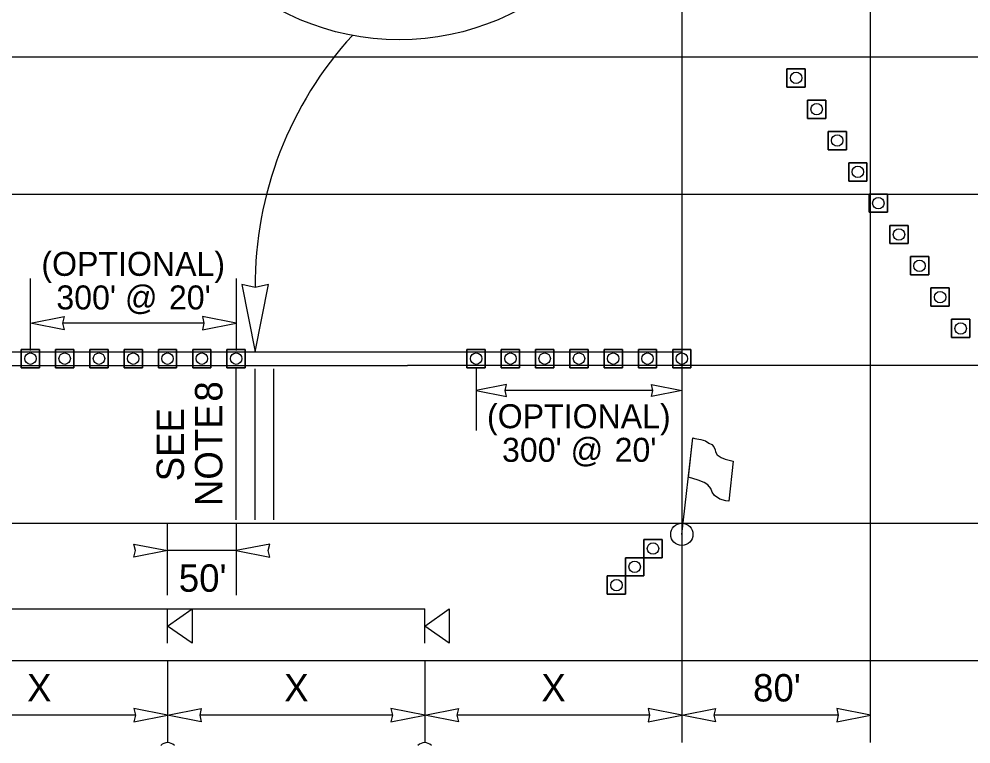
# Model space of a CAD drawing. Extents: x 99999.1 to 100095.7, y 99995 to 100010.7.
# Drawn here: x 100042.344 to 100045.12, y 100005.488 to 100007.603 of the extents above; entities that cross this region are included whole.
import ezdxf

# ---------------------------------------------------------------- set-up
doc = ezdxf.new("R2010")
doc.units = 0
for name, color, linetype in [('RD_ED_ShoulderPavedEdge', 7, 'Continuous'), ('RD_MK_LineDblYellowCenter', 7, 'Continuous'), ('RD_MK_LineEdgeWhite', 7, 'Continuous'), ('RD_MK_LineNoPass', 7, 'Continuous'), ('RD_MK_LineSkipCenter', 7, 'Continuous'), ('TR_SN_ConstructionSigns', 7, 'Continuous'), ('TR_WZ_FlaggingStation', 7, 'Continuous'), ('TR_WZ_PortableSignMountBlk-Org', 7, 'Continuous'), ('TR_WZ_TrafficCone', 7, 'Continuous'), ('TR_WZ_WorkZoneDetails', 7, 'Continuous'), ('TR_WZ_WorkZoneTextCurrent', 7, 'Continuous')]:
    doc.layers.add(name, color=color, linetype=linetype)

msp = doc.modelspace()

# ---------------------------------------------------------------- linework, layer by layer
at = {"layer": 'RD_ED_ShoulderPavedEdge'}
for p, q in [((100040.1076, 100007.4923), (100055.6424, 100007.4923)), ((100040.1076, 100005.7323), (100055.6424, 100005.7323))]:
    msp.add_line(p, q, dxfattribs=at)
at = {"layer": 'RD_MK_LineDblYellowCenter'}
for p, q in [((100040.1282, 100006.6323), (100043.4767, 100006.6323)), ((100040.0869, 100006.5923), (100043.4767, 100006.5923))]:
    msp.add_line(p, q, dxfattribs=at)
at = {"layer": 'RD_MK_LineEdgeWhite'}
for p, q in [((100040.1076, 100007.0923), (100055.6424, 100007.0923)), ((100040.1076, 100006.1323), (100055.6424, 100006.1323))]:
    msp.add_line(p, q, dxfattribs=at)
at = {"layer": 'RD_MK_LineNoPass'}
msp.add_line((100043.4767, 100006.6323), (100044.2767, 100006.6323), dxfattribs=at)
at = {"layer": 'RD_MK_LineSkipCenter'}
msp.add_lwpolyline([(100051.15, 100006.5923), (100043.4767, 100006.5923)], dxfattribs=at)
at = {"layer": 'TR_SN_ConstructionSigns'}
for centre in [(100042.7767, 100005.4642), (100043.5267, 100005.4642)]:
    msp.add_arc(centre, 0.0281, 45, 135, dxfattribs=at)
at = {"layer": 'TR_WZ_FlaggingStation'}
for p, q in [((100044.2767, 100006.0998), (100044.3087, 100006.3808)), ((100044.2957, 100006.2667), (100044.3087, 100006.3811)), ((100044.4267, 100006.3133), (100044.4134, 100006.1961)), ((100044.2957, 100006.2667), (100044.2957, 100006.2667))]:
    msp.add_line(p, q, dxfattribs=at)
for points in [[(100044.3087, 100006.3811), (100044.3145, 100006.3798), (100044.3323, 100006.3764), (100044.3461, 100006.3722), (100044.3558, 100006.3661), (100044.3643, 100006.3614), (100044.37, 100006.3546), (100044.3743, 100006.3467), (100044.3748, 100006.3405), (100044.3802, 100006.3313), (100044.391, 100006.3239), (100044.4034, 100006.3187), (100044.4267, 100006.3133)], [(100044.4134, 100006.1961), (100044.4052, 100006.1975), (100044.3876, 100006.2021), (100044.3719, 100006.2126), (100044.3654, 100006.2232), (100044.3615, 100006.2335), (100044.3524, 100006.2444), (100044.3414, 100006.2506), (100044.3241, 100006.2577), (100044.2957, 100006.2667)]]:
    msp.add_lwpolyline(points, dxfattribs=at)
msp.add_circle((100044.2767, 100006.0998), 0.0325, dxfattribs=at)
at = {"layer": 'TR_WZ_PortableSignMountBlk-Org'}
for p, q in [((100042.7767, 100005.7824), (100042.7767, 100005.8824)), ((100043.5267, 100005.7824), (100043.5267, 100005.8824))]:
    msp.add_line(p, q, dxfattribs=at)
for points in [[(100042.7767, 100005.8323), (100042.8485, 100005.8824), (100042.8485, 100005.7824)], [(100043.5267, 100005.8323), (100043.5985, 100005.8824), (100043.5985, 100005.7824)]]:
    msp.add_lwpolyline(points, close=True, dxfattribs=at)
at = {"layer": 'TR_WZ_TrafficCone'}
for points in [[(100044.6367, 100007.4577), (100044.5834, 100007.4577), (100044.5834, 100007.4043), (100044.6367, 100007.4043), (100044.6367, 100007.4577)], [(100044.6367, 100007.4043), (100044.5834, 100007.4043), (100044.5834, 100007.4577), (100044.6367, 100007.4577), (100044.6367, 100007.4043)], [(100044.6967, 100007.3663), (100044.6434, 100007.3663), (100044.6434, 100007.313), (100044.6967, 100007.313), (100044.6967, 100007.3663)], [(100044.6967, 100007.313), (100044.6434, 100007.313), (100044.6434, 100007.3663), (100044.6967, 100007.3663), (100044.6967, 100007.313)], [(100044.7567, 100007.275), (100044.7034, 100007.275), (100044.7034, 100007.2217), (100044.7567, 100007.2217), (100044.7567, 100007.275)], [(100044.7567, 100007.2217), (100044.7034, 100007.2217), (100044.7034, 100007.275), (100044.7567, 100007.275), (100044.7567, 100007.2217)], [(100044.8167, 100007.1837), (100044.7634, 100007.1837), (100044.7634, 100007.1303), (100044.8167, 100007.1303), (100044.8167, 100007.1837)], [(100044.8167, 100007.1303), (100044.7634, 100007.1303), (100044.7634, 100007.1837), (100044.8167, 100007.1837), (100044.8167, 100007.1303)], [(100044.8234, 100007.0923), (100044.8767, 100007.0923), (100044.8767, 100007.039), (100044.8234, 100007.039), (100044.8234, 100007.0923)], [(100044.8234, 100007.039), (100044.8767, 100007.039), (100044.8767, 100007.0923), (100044.8234, 100007.0923), (100044.8234, 100007.039)], [(100044.8834, 100007.001), (100044.9367, 100007.001), (100044.9367, 100006.9477), (100044.8834, 100006.9477), (100044.8834, 100007.001)], [(100044.8834, 100006.9477), (100044.9367, 100006.9477), (100044.9367, 100007.001), (100044.8834, 100007.001), (100044.8834, 100006.9477)], [(100044.9434, 100006.9097), (100044.9967, 100006.9097), (100044.9967, 100006.8563), (100044.9434, 100006.8563), (100044.9434, 100006.9097)], [(100044.9434, 100006.8563), (100044.9967, 100006.8563), (100044.9967, 100006.9097), (100044.9434, 100006.9097), (100044.9434, 100006.8563)], [(100045.0034, 100006.8183), (100045.0567, 100006.8183), (100045.0567, 100006.765), (100045.0034, 100006.765), (100045.0034, 100006.8183)], [(100045.0034, 100006.765), (100045.0567, 100006.765), (100045.0567, 100006.8183), (100045.0034, 100006.8183), (100045.0034, 100006.765)], [(100045.0634, 100006.727), (100045.1167, 100006.727), (100045.1167, 100006.6737), (100045.0634, 100006.6737), (100045.0634, 100006.727)], [(100045.0634, 100006.6737), (100045.1167, 100006.6737), (100045.1167, 100006.727), (100045.0634, 100006.727), (100045.0634, 100006.6737)], [(100042.4033, 100006.639), (100042.35, 100006.639), (100042.35, 100006.5857), (100042.4033, 100006.5857), (100042.4033, 100006.639)], [(100042.4033, 100006.5857), (100042.35, 100006.5857), (100042.35, 100006.639), (100042.4033, 100006.639), (100042.4033, 100006.5857)], [(100042.5033, 100006.639), (100042.45, 100006.639), (100042.45, 100006.5857), (100042.5033, 100006.5857), (100042.5033, 100006.639)], [(100042.5033, 100006.5857), (100042.45, 100006.5857), (100042.45, 100006.639), (100042.5033, 100006.639), (100042.5033, 100006.5857)], [(100042.6033, 100006.639), (100042.55, 100006.639), (100042.55, 100006.5857), (100042.6033, 100006.5857), (100042.6033, 100006.639)], [(100042.6033, 100006.5857), (100042.55, 100006.5857), (100042.55, 100006.639), (100042.6033, 100006.639), (100042.6033, 100006.5857)], [(100042.7033, 100006.639), (100042.65, 100006.639), (100042.65, 100006.5857), (100042.7033, 100006.5857), (100042.7033, 100006.639)], [(100042.7033, 100006.5857), (100042.65, 100006.5857), (100042.65, 100006.639), (100042.7033, 100006.639), (100042.7033, 100006.5857)], [(100042.8033, 100006.639), (100042.75, 100006.639), (100042.75, 100006.5857), (100042.8033, 100006.5857), (100042.8033, 100006.639)], [(100042.8033, 100006.5857), (100042.75, 100006.5857), (100042.75, 100006.639), (100042.8033, 100006.639), (100042.8033, 100006.5857)], [(100042.9033, 100006.639), (100042.85, 100006.639), (100042.85, 100006.5857), (100042.9033, 100006.5857), (100042.9033, 100006.639)], [(100042.9033, 100006.5857), (100042.85, 100006.5857), (100042.85, 100006.639), (100042.9033, 100006.639), (100042.9033, 100006.5857)], [(100043.0033, 100006.639), (100042.95, 100006.639), (100042.95, 100006.5857), (100043.0033, 100006.5857), (100043.0033, 100006.639)], [(100043.0033, 100006.5857), (100042.95, 100006.5857), (100042.95, 100006.639), (100043.0033, 100006.639), (100043.0033, 100006.5857)], [(100043.7033, 100006.639), (100043.65, 100006.639), (100043.65, 100006.5857), (100043.7033, 100006.5857), (100043.7033, 100006.639)], [(100043.7033, 100006.5857), (100043.65, 100006.5857), (100043.65, 100006.639), (100043.7033, 100006.639), (100043.7033, 100006.5857)], [(100043.8033, 100006.639), (100043.75, 100006.639), (100043.75, 100006.5857), (100043.8033, 100006.5857), (100043.8033, 100006.639)], [(100043.8033, 100006.5857), (100043.75, 100006.5857), (100043.75, 100006.639), (100043.8033, 100006.639), (100043.8033, 100006.5857)], [(100043.9033, 100006.639), (100043.85, 100006.639), (100043.85, 100006.5857), (100043.9033, 100006.5857), (100043.9033, 100006.639)], [(100043.9033, 100006.5857), (100043.85, 100006.5857), (100043.85, 100006.639), (100043.9033, 100006.639), (100043.9033, 100006.5857)], [(100044.0033, 100006.639), (100043.95, 100006.639), (100043.95, 100006.5857), (100044.0033, 100006.5857), (100044.0033, 100006.639)], [(100044.0033, 100006.5857), (100043.95, 100006.5857), (100043.95, 100006.639), (100044.0033, 100006.639), (100044.0033, 100006.5857)], [(100044.1033, 100006.639), (100044.05, 100006.639), (100044.05, 100006.5857), (100044.1033, 100006.5857), (100044.1033, 100006.639)], [(100044.1033, 100006.5857), (100044.05, 100006.5857), (100044.05, 100006.639), (100044.1033, 100006.639), (100044.1033, 100006.5857)], [(100044.2033, 100006.639), (100044.15, 100006.639), (100044.15, 100006.5857), (100044.2033, 100006.5857), (100044.2033, 100006.639)], [(100044.2033, 100006.5857), (100044.15, 100006.5857), (100044.15, 100006.639), (100044.2033, 100006.639), (100044.2033, 100006.5857)], [(100044.3033, 100006.639), (100044.25, 100006.639), (100044.25, 100006.5857), (100044.3033, 100006.5857), (100044.3033, 100006.639)], [(100044.3033, 100006.5857), (100044.25, 100006.5857), (100044.25, 100006.639), (100044.3033, 100006.639), (100044.3033, 100006.5857)], [(100044.166, 100006.085), (100044.2193, 100006.085), (100044.2193, 100006.0317), (100044.166, 100006.0317), (100044.166, 100006.085)], [(100044.166, 100006.0317), (100044.2193, 100006.0317), (100044.2193, 100006.085), (100044.166, 100006.085), (100044.166, 100006.0317)], [(100044.1127, 100006.0317), (100044.166, 100006.0317), (100044.166, 100005.9783), (100044.1127, 100005.9783), (100044.1127, 100006.0317)], [(100044.1127, 100005.9783), (100044.166, 100005.9783), (100044.166, 100006.0317), (100044.1127, 100006.0317), (100044.1127, 100005.9783)], [(100044.0593, 100005.9783), (100044.1127, 100005.9783), (100044.1127, 100005.925), (100044.0593, 100005.925), (100044.0593, 100005.9783)], [(100044.0593, 100005.925), (100044.1127, 100005.925), (100044.1127, 100005.9783), (100044.0593, 100005.9783), (100044.0593, 100005.925)]]:
    msp.add_lwpolyline(points, dxfattribs=at)
for centre in [(100044.61, 100007.431), (100044.67, 100007.3397), (100044.73, 100007.2483), (100044.79, 100007.157), (100044.85, 100007.0657), (100044.91, 100006.9743), (100044.97, 100006.883), (100045.03, 100006.7917), (100045.09, 100006.7003), (100042.3767, 100006.6123), (100042.4767, 100006.6123), (100042.5767, 100006.6123), (100042.6767, 100006.6123), (100042.7767, 100006.6123), (100042.8767, 100006.6123), (100042.9767, 100006.6123), (100043.6767, 100006.6123), (100043.7767, 100006.6123), (100043.8767, 100006.6123), (100043.9767, 100006.6123), (100044.0767, 100006.6123), (100044.1767, 100006.6123), (100044.2767, 100006.6123), (100044.1927, 100006.0583), (100044.1393, 100006.005), (100044.086, 100005.9517)]:
    msp.add_circle(centre, 0.0167, dxfattribs=at)
at = {"layer": 'TR_WZ_WorkZoneDetails'}
for p, q in [((100044.2767, 100008.9491), (100044.2767, 100005.4923)), ((100044.8267, 100005.4923), (100044.8267, 100007.7323)), ((100042.3767, 100006.6357), (100042.3767, 100006.8457)), ((100042.9767, 100006.8457), (100042.9767, 100006.6357)), ((100042.8829, 100006.7157), (100042.4704, 100006.7157)), ((100042.9767, 100006.1423), (100042.9767, 100006.5823)), ((100043.0323, 100006.1423), (100043.0323, 100006.5823)), ((100043.0872, 100006.1423), (100043.0872, 100006.5823)), ((100043.6767, 100006.5857), (100043.6767, 100006.4023)), ((100044.2767, 100006.5857), (100044.2767, 100006.4023)), ((100044.1923, 100006.5193), (100043.761, 100006.5193)), ((100042.7767, 100005.9223), (100042.7767, 100006.1323)), ((100042.9767, 100006.1323), (100042.9767, 100005.9223)), ((100042.9767, 100006.0523), (100042.7767, 100006.0523)), ((100040.5267, 100005.8824), (100043.5267, 100005.8824)), ((100042.7767, 100005.7323), (100042.7767, 100005.4923)), ((100043.5267, 100005.7323), (100043.5267, 100005.4923)), ((100042.6829, 100005.5723), (100042.1204, 100005.5723)), ((100043.4329, 100005.5723), (100042.8704, 100005.5723)), ((100044.1829, 100005.5723), (100043.6204, 100005.5723)), ((100044.7329, 100005.5723), (100044.3704, 100005.5723))]:
    msp.add_line(p, q, dxfattribs=at)
for points in [[(100043.0323, 100006.6323), (100043.0708, 100006.8289), (100043.0323, 100006.8198), (100042.9937, 100006.8289)], [(100042.3767, 100006.7157), (100042.4749, 100006.7349), (100042.4704, 100006.7157), (100042.4749, 100006.6964)], [(100042.9767, 100006.7157), (100042.8784, 100006.7349), (100042.8829, 100006.7157), (100042.8784, 100006.6964)], [(100043.6767, 100006.5193), (100043.7651, 100006.502), (100043.761, 100006.5193), (100043.7651, 100006.5367)], [(100044.2767, 100006.5193), (100044.1882, 100006.502), (100044.1923, 100006.5193), (100044.1882, 100006.5367)], [(100042.7767, 100006.0523), (100042.6784, 100006.0331), (100042.6829, 100006.0523), (100042.6784, 100006.0716)], [(100042.9767, 100006.0523), (100043.0749, 100006.0331), (100043.0704, 100006.0523), (100043.0749, 100006.0716)], [(100042.7767, 100005.5723), (100042.6784, 100005.5916), (100042.6829, 100005.5723), (100042.6784, 100005.5531)], [(100042.7767, 100005.5723), (100042.8749, 100005.5916), (100042.8704, 100005.5723), (100042.8749, 100005.5531)], [(100043.5267, 100005.5723), (100043.4284, 100005.5916), (100043.4329, 100005.5723), (100043.4284, 100005.5531)], [(100043.5267, 100005.5723), (100043.6249, 100005.5916), (100043.6204, 100005.5723), (100043.6249, 100005.5531)], [(100044.2767, 100005.5723), (100044.1784, 100005.5916), (100044.1829, 100005.5723), (100044.1784, 100005.5531)], [(100044.2767, 100005.5723), (100044.3749, 100005.5916), (100044.3704, 100005.5723), (100044.3749, 100005.5531)], [(100044.8267, 100005.5723), (100044.7284, 100005.5916), (100044.7329, 100005.5723), (100044.7284, 100005.5531)]]:
    msp.add_lwpolyline(points, close=True, dxfattribs=at)
msp.add_circle((100043.4522, 100008.2843), 0.742, dxfattribs=at)
msp.add_arc((100044.1081, 100006.8268), 1.0759, 137.408, 180.3733, dxfattribs=at)

# ---------------------------------------------------------------- texts
for s, p in [('8', (100042.9367, 100006.4868)), ('NOTE', (100042.9367, 100006.182)), ('SEE', (100042.8247, 100006.2544))]:
    msp.add_text(s, height=0.08, rotation=90, dxfattribs=at).set_placement(p)
at = {"layer": 'TR_WZ_WorkZoneTextCurrent'}
for s, height, p in [('(OPTIONAL)', 0.07, (100042.4087, 100006.8537)), ("300' @", 0.07, (100042.4524, 100006.7557)), ("20'", 0.07, (100042.7808, 100006.7557)), ('(OPTIONAL)', 0.07, (100043.7085, 100006.4093)), ("300' @", 0.07, (100043.7523, 100006.3113)), ("20'", 0.07, (100044.0807, 100006.3113)), ("50'", 0.08, (100042.8094, 100005.9323))]:
    msp.add_text(s, height=height, dxfattribs=at).set_placement(p)
for s, p in [('X', (100042.3669, 100005.6123)), ('X', (100043.1169, 100005.6123)), ('X', (100043.8669, 100005.6123)), ("80'", (100044.4844, 100005.6123))]:
    msp.add_text(s, height=0.08, rotation=360, dxfattribs=at).set_placement(p)

doc.saveas('drawing.dxf')
